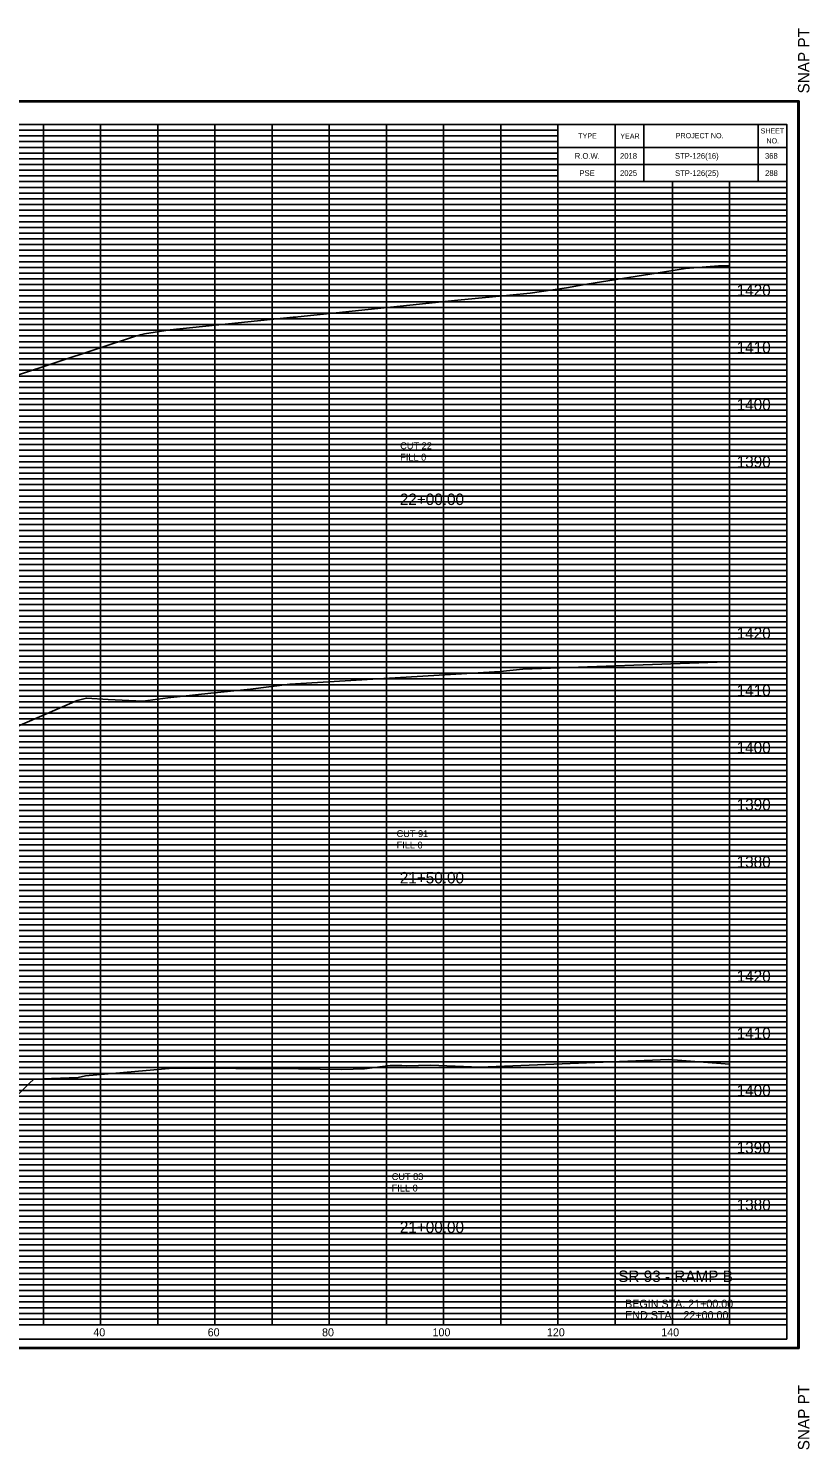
# Model space of a CAD drawing. Extents: x 980 to 1324, y 978 to 1497.
# Drawn here: x 1187.4 to 1324, y 978.2 to 1226.8 of the extents above; entities that cross this region are included whole.
import ezdxf

# ---------------------------------------------------------------- set-up
doc = ezdxf.new("R2010")
doc.units = 0
for name, color, linetype in [('DESIGN - SCRATCH - User 1', 7, 'Continuous'), ('DESIGN - SHEET - Corner Text', 7, 'Continuous'), ('DESIGN - SHEET - Light Grid', 7, 'Continuous'), ('DESIGN - SHEET - Linework', 7, 'Continuous'), ('DESIGN - SHEET - Plot Shape', 7, 'Continuous'), ('DESIGN - TYPICAL - Text', 7, 'Continuous'), ('SURVEY - GROUND - Top of Ground', 7, 'Continuous')]:
    doc.layers.add(name, color=color, linetype=linetype)

# ---------------------------------------------------------------- blocks, each defined once
blk = doc.blocks.new('XSTSHT')
at = {"layer": 'DESIGN - SCRATCH - User 1'}
for p, q in [((28.5, 20.45), (28.5, 20.45)), ((29.24, 20.45), (29.24, 20.45)), ((30.49, 20.45), (30.49, 20.45)), ((31.74, 20.45), (31.74, 20.45)), ((28.5, 20.15), (28.5, 20.15)), ((29.24, 20.15), (29.24, 20.15)), ((30.49, 20.15), (30.49, 20.15)), ((31.74, 20.15), (31.74, 20.15))]:
    blk.add_line(p, q, dxfattribs=at)
at = {"layer": 'DESIGN - SHEET - Light Grid'}
for p, q in [((16, 20.9), (24, 20.9)), ((24, 20.9), (28, 20.9)), ((16, 20.8), (24, 20.8)), ((16, 20.7), (24, 20.7)), ((24, 20.8), (28, 20.8)), ((24, 20.7), (28, 20.7)), ((16, 20.6), (24, 20.6)), ((16, 20.5), (24, 20.5)), ((16, 20.4), (24, 20.4)), ((24, 20.6), (28, 20.6)), ((24, 20.5), (28, 20.5)), ((24, 20.4), (28, 20.4)), ((16, 20.3), (24, 20.3)), ((16, 20.2), (24, 20.2)), ((24, 20.3), (28, 20.3)), ((24, 20.2), (28, 20.2)), ((16, 20.1), (24, 20.1)), ((16, 19.9), (24, 19.9)), ((24, 20.1), (28, 20.1)), ((24, 19.9), (32, 19.9)), ((16, 19.8), (24, 19.8)), ((16, 19.7), (24, 19.7)), ((24, 19.8), (32, 19.8)), ((24, 19.7), (32, 19.7)), ((16, 19.6), (24, 19.6)), ((16, 19.5), (24, 19.5)), ((16, 19.4), (24, 19.4)), ((24, 19.6), (32, 19.6)), ((24, 19.5), (32, 19.5)), ((24, 19.4), (32, 19.4)), ((16, 19.3), (24, 19.3)), ((16, 19.2), (24, 19.2)), ((24, 19.3), (32, 19.3)), ((24, 19.2), (32, 19.2)), ((16, 19.1), (24, 19.1)), ((16, 18.9), (24, 18.9)), ((24, 19.1), (32, 19.1)), ((24, 18.9), (32, 18.9)), ((16, 18.8), (24, 18.8)), ((16, 18.7), (24, 18.7)), ((24, 18.8), (32, 18.8)), ((24, 18.7), (32, 18.7)), ((16, 18.6), (24, 18.6)), ((16, 18.5), (24, 18.5)), ((16, 18.4), (24, 18.4)), ((24, 18.6), (32, 18.6)), ((24, 18.5), (32, 18.5)), ((24, 18.4), (32, 18.4)), ((16, 18.3), (24, 18.3)), ((16, 18.2), (24, 18.2)), ((24, 18.3), (32, 18.3)), ((24, 18.2), (32, 18.2)), ((16, 18.1), (24, 18.1)), ((24, 18.1), (32, 18.1)), ((16, 17.9), (24, 17.9)), ((16, 17.8), (24, 17.8)), ((16, 17.7), (24, 17.7)), ((24, 17.9), (32, 17.9)), ((24, 17.8), (32, 17.8)), ((24, 17.7), (32, 17.7)), ((16, 17.6), (24, 17.6)), ((16, 17.5), (24, 17.5)), ((24, 17.6), (32, 17.6)), ((24, 17.5), (32, 17.5)), ((16, 17.4), (24, 17.4)), ((16, 17.3), (24, 17.3)), ((16, 17.2), (24, 17.2)), ((24, 17.4), (32, 17.4)), ((24, 17.3), (32, 17.3)), ((24, 17.2), (32, 17.2)), ((16, 17.1), (24, 17.1)), ((24, 17.1), (32, 17.1)), ((16, 16.9), (24, 16.9)), ((16, 16.8), (24, 16.8)), ((16, 16.7), (24, 16.7)), ((24, 16.9), (32, 16.9)), ((24, 16.8), (32, 16.8)), ((24, 16.7), (32, 16.7)), ((16, 16.6), (24, 16.6)), ((16, 16.5), (24, 16.5)), ((24, 16.6), (32, 16.6)), ((24, 16.5), (32, 16.5)), ((16, 16.4), (24, 16.4)), ((16, 16.3), (24, 16.3)), ((16, 16.2), (24, 16.2)), ((24, 16.4), (32, 16.4)), ((24, 16.3), (32, 16.3)), ((24, 16.2), (32, 16.2)), ((16, 16.1), (24, 16.1)), ((24, 16.1), (32, 16.1)), ((16, 15.9), (24, 15.9)), ((16, 15.8), (24, 15.8)), ((16, 15.7), (24, 15.7)), ((24, 15.9), (32, 15.9)), ((24, 15.8), (32, 15.8)), ((24, 15.7), (32, 15.7)), ((16, 15.6), (24, 15.6)), ((16, 15.5), (24, 15.5)), ((24, 15.6), (32, 15.6)), ((24, 15.5), (32, 15.5)), ((16, 15.4), (24, 15.4)), ((16, 15.3), (24, 15.3)), ((16, 15.2), (24, 15.2)), ((24, 15.4), (32, 15.4)), ((24, 15.3), (32, 15.3)), ((24, 15.2), (32, 15.2)), ((16, 15.1), (24, 15.1)), ((24, 15.1), (32, 15.1)), ((16, 14.9), (24, 14.9)), ((16, 14.8), (24, 14.8)), ((16, 14.7), (24, 14.7)), ((24, 14.9), (32, 14.9)), ((24, 14.8), (32, 14.8)), ((24, 14.7), (32, 14.7)), ((16, 14.6), (24, 14.6)), ((16, 14.5), (24, 14.5)), ((24, 14.6), (32, 14.6)), ((24, 14.5), (32, 14.5)), ((16, 14.4), (24, 14.4)), ((16, 14.3), (24, 14.3)), ((16, 14.2), (24, 14.2)), ((24, 14.4), (32, 14.4)), ((24, 14.3), (32, 14.3)), ((24, 14.2), (32, 14.2)), ((16, 14.1), (24, 14.1)), ((24, 14.1), (32, 14.1)), ((16, 13.9), (24, 13.9)), ((16, 13.8), (24, 13.8)), ((16, 13.7), (24, 13.7)), ((24, 13.9), (32, 13.9)), ((24, 13.8), (32, 13.8)), ((24, 13.7), (32, 13.7)), ((16, 13.6), (24, 13.6)), ((16, 13.5), (24, 13.5)), ((24, 13.6), (32, 13.6)), ((24, 13.5), (32, 13.5)), ((16, 13.4), (24, 13.4)), ((16, 13.3), (24, 13.3)), ((16, 13.2), (24, 13.2)), ((24, 13.4), (32, 13.4)), ((24, 13.3), (32, 13.3)), ((24, 13.2), (32, 13.2)), ((16, 13.1), (24, 13.1)), ((24, 13.1), (32, 13.1)), ((16, 12.9), (24, 12.9)), ((16, 12.8), (24, 12.8)), ((16, 12.7), (24, 12.7)), ((24, 12.9), (32, 12.9)), ((24, 12.8), (32, 12.8)), ((24, 12.7), (32, 12.7)), ((16, 12.6), (24, 12.6)), ((16, 12.5), (24, 12.5)), ((24, 12.6), (32, 12.6)), ((24, 12.5), (32, 12.5)), ((16, 12.4), (24, 12.4)), ((16, 12.3), (24, 12.3)), ((16, 12.2), (24, 12.2)), ((24, 12.4), (32, 12.4)), ((24, 12.3), (32, 12.3)), ((24, 12.2), (32, 12.2)), ((16, 12.1), (24, 12.1)), ((24, 12.1), (32, 12.1)), ((16, 11.9), (24, 11.9)), ((16, 11.8), (24, 11.8)), ((16, 11.7), (24, 11.7)), ((24, 11.9), (32, 11.9)), ((24, 11.8), (32, 11.8)), ((24, 11.7), (32, 11.7)), ((16, 11.6), (24, 11.6)), ((16, 11.5), (24, 11.5)), ((24, 11.6), (32, 11.6)), ((24, 11.5), (32, 11.5)), ((16, 11.4), (24, 11.4)), ((16, 11.3), (24, 11.3)), ((16, 11.2), (24, 11.2)), ((24, 11.4), (32, 11.4)), ((24, 11.3), (32, 11.3)), ((24, 11.2), (32, 11.2)), ((16, 11.1), (24, 11.1)), ((24, 11.1), (32, 11.1)), ((16, 10.9), (24, 10.9)), ((16, 10.8), (24, 10.8)), ((16, 10.7), (24, 10.7)), ((24, 10.9), (32, 10.9)), ((24, 10.8), (32, 10.8)), ((24, 10.7), (32, 10.7)), ((16, 10.6), (24, 10.6)), ((16, 10.5), (24, 10.5)), ((24, 10.6), (32, 10.6)), ((24, 10.5), (32, 10.5)), ((16, 10.4), (24, 10.4)), ((16, 10.3), (24, 10.3)), ((16, 10.2), (24, 10.2)), ((24, 10.4), (32, 10.4)), ((24, 10.3), (32, 10.3)), ((24, 10.2), (32, 10.2)), ((16, 10.1), (24, 10.1)), ((24, 10.1), (32, 10.1)), ((16, 9.9), (24, 9.9)), ((16, 9.8), (24, 9.8)), ((16, 9.7), (24, 9.7)), ((24, 9.9), (32, 9.9)), ((24, 9.8), (32, 9.8)), ((24, 9.7), (32, 9.7)), ((16, 9.6), (24, 9.6)), ((16, 9.5), (24, 9.5)), ((24, 9.6), (32, 9.6)), ((24, 9.5), (32, 9.5)), ((16, 9.4), (24, 9.4)), ((16, 9.3), (24, 9.3)), ((16, 9.2), (24, 9.2)), ((24, 9.4), (32, 9.4)), ((24, 9.3), (32, 9.3)), ((24, 9.2), (32, 9.2)), ((16, 9.1), (24, 9.1)), ((24, 9.1), (32, 9.1)), ((16, 8.9), (24, 8.9)), ((16, 8.8), (24, 8.8)), ((24, 8.9), (32, 8.9)), ((24, 8.8), (32, 8.8)), ((16, 8.7), (24, 8.7)), ((16, 8.6), (24, 8.6)), ((16, 8.5), (24, 8.5)), ((24, 8.7), (32, 8.7)), ((24, 8.6), (32, 8.6)), ((24, 8.5), (32, 8.5)), ((16, 8.4), (24, 8.4)), ((16, 8.3), (24, 8.3)), ((24, 8.4), (32, 8.4)), ((24, 8.3), (32, 8.3)), ((16, 8.2), (24, 8.2)), ((16, 8.1), (24, 8.1)), ((24, 8.2), (32, 8.2)), ((24, 8.1), (32, 8.1)), ((16, 7.9), (24, 7.9)), ((16, 7.8), (24, 7.8)), ((24, 7.9), (32, 7.9)), ((24, 7.8), (32, 7.8)), ((16, 7.7), (24, 7.7)), ((16, 7.6), (24, 7.6)), ((16, 7.5), (24, 7.5)), ((24, 7.7), (32, 7.7)), ((24, 7.6), (32, 7.6)), ((24, 7.5), (32, 7.5)), ((16, 7.4), (24, 7.4)), ((16, 7.3), (24, 7.3)), ((24, 7.4), (32, 7.4)), ((24, 7.3), (32, 7.3)), ((16, 7.2), (24, 7.2)), ((16, 7.1), (24, 7.1)), ((24, 7.2), (32, 7.2)), ((24, 7.1), (32, 7.1)), ((16, 6.9), (24, 6.9)), ((16, 6.8), (24, 6.8)), ((24, 6.9), (32, 6.9)), ((24, 6.8), (32, 6.8)), ((16, 6.7), (24, 6.7)), ((16, 6.6), (24, 6.6)), ((16, 6.5), (24, 6.5)), ((24, 6.7), (32, 6.7)), ((24, 6.6), (32, 6.6)), ((24, 6.5), (32, 6.5)), ((16, 6.4), (24, 6.4)), ((16, 6.3), (24, 6.3)), ((24, 6.4), (32, 6.4)), ((24, 6.3), (32, 6.3)), ((16, 6.2), (24, 6.2)), ((16, 6.1), (24, 6.1)), ((24, 6.2), (32, 6.2)), ((24, 6.1), (32, 6.1)), ((16, 5.9), (24, 5.9)), ((16, 5.8), (24, 5.8)), ((24, 5.9), (32, 5.9)), ((24, 5.8), (32, 5.8)), ((16, 5.7), (24, 5.7)), ((16, 5.6), (24, 5.6)), ((16, 5.5), (24, 5.5)), ((24, 5.7), (32, 5.7)), ((24, 5.6), (32, 5.6)), ((24, 5.5), (32, 5.5)), ((16, 5.4), (24, 5.4)), ((16, 5.3), (24, 5.3)), ((24, 5.4), (32, 5.4)), ((24, 5.3), (32, 5.3)), ((16, 5.2), (24, 5.2)), ((16, 5.1), (24, 5.1)), ((24, 5.2), (32, 5.2)), ((24, 5.1), (32, 5.1)), ((16, 4.9), (24, 4.9)), ((16, 4.8), (24, 4.8)), ((24, 4.9), (32, 4.9)), ((24, 4.8), (32, 4.8)), ((16, 4.7), (24, 4.7)), ((16, 4.6), (24, 4.6)), ((16, 4.5), (24, 4.5)), ((24, 4.7), (32, 4.7)), ((24, 4.6), (32, 4.6)), ((24, 4.5), (32, 4.5)), ((16, 4.4), (24, 4.4)), ((16, 4.3), (24, 4.3)), ((24, 4.4), (32, 4.4)), ((24, 4.3), (32, 4.3)), ((16, 4.2), (24, 4.2)), ((16, 4.1), (24, 4.1)), ((24, 4.2), (32, 4.2)), ((24, 4.1), (32, 4.1)), ((16, 3.9), (24, 3.9)), ((16, 3.8), (24, 3.8)), ((24, 3.9), (32, 3.9)), ((24, 3.8), (32, 3.8)), ((16, 3.7), (24, 3.7)), ((16, 3.6), (24, 3.6)), ((16, 3.5), (24, 3.5)), ((24, 3.7), (32, 3.7)), ((24, 3.6), (32, 3.6)), ((24, 3.5), (32, 3.5)), ((16, 3.4), (24, 3.4)), ((16, 3.3), (24, 3.3)), ((24, 3.4), (32, 3.4)), ((24, 3.3), (32, 3.3)), ((16, 3.2), (24, 3.2)), ((16, 3.1), (24, 3.1)), ((24, 3.2), (32, 3.2)), ((24, 3.1), (32, 3.1)), ((16, 2.9), (24, 2.9)), ((16, 2.8), (24, 2.8)), ((24, 2.9), (32, 2.9)), ((24, 2.8), (32, 2.8)), ((16, 2.7), (24, 2.7)), ((16, 2.6), (24, 2.6)), ((16, 2.5), (24, 2.5)), ((24, 2.7), (32, 2.7)), ((24, 2.6), (32, 2.6)), ((24, 2.5), (32, 2.5)), ((16, 2.4), (24, 2.4)), ((16, 2.3), (24, 2.3)), ((24, 2.4), (32, 2.4)), ((24, 2.3), (32, 2.3)), ((16, 2.2), (24, 2.2)), ((16, 2.1), (24, 2.1)), ((24, 2.2), (32, 2.2)), ((24, 2.1), (32, 2.1)), ((16, 1.9), (24, 1.9)), ((16, 1.8), (24, 1.8)), ((24, 1.9), (32, 1.9)), ((24, 1.8), (32, 1.8)), ((16, 1.7), (24, 1.7)), ((16, 1.6), (24, 1.6)), ((16, 1.5), (24, 1.5)), ((24, 1.7), (32, 1.7)), ((24, 1.6), (32, 1.6)), ((24, 1.5), (32, 1.5)), ((16, 1.4), (24, 1.4)), ((16, 1.3), (24, 1.3)), ((24, 1.4), (32, 1.4)), ((24, 1.3), (32, 1.3)), ((16, 1.2), (24, 1.2)), ((16, 1.1), (24, 1.1)), ((24, 1.2), (32, 1.2)), ((24, 1.1), (32, 1.1)), ((16, 0.9), (24, 0.9)), ((16, 0.8), (24, 0.8)), ((24, 0.9), (32, 0.9)), ((24, 0.8), (32, 0.8)), ((16, 0.7), (24, 0.7)), ((16, 0.6), (24, 0.6)), ((16, 0.5), (24, 0.5)), ((24, 0.7), (32, 0.7)), ((24, 0.6), (32, 0.6)), ((24, 0.5), (32, 0.5)), ((16, 0.4), (24, 0.4)), ((16, 0.3), (24, 0.3)), ((24, 0.4), (32, 0.4)), ((24, 0.3), (32, 0.3)), ((16, 0.2), (24, 0.2)), ((16, 0.1), (24, 0.1)), ((24, 0.2), (32, 0.2)), ((24, 0.1), (32, 0.1))]:
    blk.add_line(p, q, dxfattribs=at)
at = {"layer": 'DESIGN - SHEET - Linework'}
for p, q in [((-1.823, 21.414), (32.217, 21.414)), ((32.217, 21.414), (32.217, -0.414)), ((19, 0), (19, 21)), ((20, 0), (20, 21)), ((21, 0), (21, 21)), ((22, 0), (22, 21)), ((23, 0), (23, 21)), ((24, 0), (24, 21)), ((25, 0), (25, 21)), ((26, 0), (26, 21)), ((27, 0), (27, 21)), ((0, 20), (28, 20)), ((28, 0), (28, 20)), ((29, 0), (29, 20)), ((30, 0), (30, 20)), ((31, 0), (31, 20)), ((0, 19), (32, 19)), ((0, 18), (32, 18)), ((0, 17), (32, 17)), ((0, 16), (32, 16)), ((0, 15), (32, 15)), ((0, 14), (32, 14)), ((0, 13), (32, 13)), ((0, 12), (32, 12)), ((0, 11), (32, 11)), ((0, 10), (32, 10)), ((0, 9), (32, 9)), ((0, 8), (32, 8)), ((0, 7), (32, 7)), ((0, 6), (32, 6)), ((0, 5), (32, 5)), ((0, 4), (32, 4)), ((0, 3), (32, 3)), ((0, 2), (32, 2)), ((0, 1), (32, 1)), ((-1.823, -0.414), (32.217, -0.414))]:
    blk.add_line(p, q, dxfattribs=at)
for points in [[(0, 21), (0, 0), (32, 0), (32, 21), (0, 21)], [(28, 21), (28, 20), (32, 20), (32, 21), (31.5, 21), (31.5, 20), (29.5, 20), (29.5, 21), (29, 21), (29, 20), (32, 20), (28, 20), (28, 20.3), (32, 20.3), (32, 20.6), (28, 20.6)]]:
    blk.add_lwpolyline(points, dxfattribs=at)
at = {"layer": 'DESIGN - SHEET - Plot Shape'}
for points in [[(-1.803, 21.394), (32.197, 21.394), (32.197, -0.394), (-1.803, -0.394)], [(-0.85, 21), (32, 21), (32, -0.25), (-0.85, -0.25)]]:
    blk.add_lwpolyline(points, close=True, dxfattribs=at)
at = {"layer": 'DESIGN - SHEET - Corner Text'}
for s, p in [('  SNAP PT', (32.397, 21.394)), ('SNAP PT  ', (32.397, -2.194))]:
    blk.add_text(s, height=0.2, rotation=90, dxfattribs=at).set_placement(p)
for s, p in [('SHEET', (31.543, 20.843)), ('TYPE', (28.354, 20.756)), ('YEAR', (29.09, 20.752)), ('PROJECT NO.', (30.06, 20.76)), ('NO.', (31.646, 20.669))]:
    blk.add_text(s, height=0.09, dxfattribs=at).set_placement(p)

msp = doc.modelspace()

# ---------------------------------------------------------------- linework, layer by layer
at = {"layer": 'DESIGN - SHEET - Plot Shape'}
msp.add_lwpolyline([(991.5, 997.5), (1320, 997.5), (1320, 1210), (991.5, 1210)], close=True, dxfattribs=at)
at = {"layer": 'SURVEY - GROUND - Top of Ground'}
for points in [[(1164.27, 1159.14), (1206.27, 1173.02), (1206.99, 1173.22), (1207.71, 1173.36), (1212.2, 1174.1), (1233.68, 1176.27), (1234.2, 1176.31), (1234.5, 1176.34), (1243.98, 1177.34), (1262.49, 1179.29), (1271.56, 1180.16), (1275.12, 1180.49), (1281.51, 1181.44), (1285.05, 1182.09), (1302.32, 1184.81), (1308.06, 1185.26), (1310, 1185.28)], [(1164.36, 1095.59), (1195.93, 1109.23), (1197.53, 1109.66), (1201.33, 1109.39), (1207.41, 1109.12), (1211.76, 1109.71), (1219.28, 1110.5), (1226.24, 1111.24), (1233.1, 1112.11), (1269.87, 1114.33), (1273.88, 1114.72), (1309.47, 1116), (1310, 1116.02)], [(1174.82, 1029.58), (1187.53, 1042.21), (1188.33, 1042.98), (1196.11, 1043.28), (1197.38, 1043.57), (1212.65, 1044.9), (1234.61, 1044.78), (1242.19, 1044.66), (1246.19, 1044.81), (1250.63, 1045.38), (1252.71, 1045.38), (1253.53, 1045.31), (1257.71, 1045.43), (1266.36, 1045.07), (1299.4, 1046.42), (1310, 1045.6)]]:
    msp.add_lwpolyline(points, dxfattribs=at)

# ---------------------------------------------------------------- block references
at = {"layer": 'DESIGN - SHEET - Corner Text', "xscale": 10, "yscale": 10}
msp.add_blockref('XSTSHT', (1000, 1000), dxfattribs=at)

# ---------------------------------------------------------------- texts
at = {"layer": 'DESIGN - SHEET - Corner Text'}
for s, height, p in [('R.O.W.', 1, (1282.94, 1204)), ('2018', 1, (1290.85, 1204)), ('STP-126(16)', 1, (1300.45, 1204)), ('368', 1, (1316.2, 1204)), ('PSE', 1, (1283.75, 1201)), ('2025', 1, (1290.85, 1201)), ('STP-126(25)', 1, (1300.47, 1201)), ('288', 1, (1316.22, 1201)), ('1420', 2, (1311.25, 1180)), ('1410', 2, (1311.25, 1170)), ('1400', 2, (1311.25, 1160)), ('1390', 2, (1311.25, 1150)), ('22+00.00', 2, (1252.34, 1143.43)), ('1420', 2, (1311.25, 1120)), ('1410', 2, (1311.25, 1110)), ('1400', 2, (1311.25, 1100)), ('1390', 2, (1311.25, 1090)), ('1380', 2, (1311.25, 1080)), ('21+50.00', 2, (1252.34, 1077.23)), ('1420', 2, (1311.25, 1060)), ('1410', 2, (1311.25, 1050)), ('1400', 2, (1311.25, 1040)), ('1390', 2, (1311.25, 1030)), ('1380', 2, (1311.25, 1020)), ('21+00.00', 2, (1252.34, 1016.08)), ('SR 93 - RAMP B', 2, (1290.53, 1007.5)), ('BEGIN STA. 21+00.00', 1.4, (1291.75, 1003)), ('END STA.   22+00.00', 1.4, (1291.75, 1001)), ('40', 1.4, (1198.74, 998)), ('60', 1.4, (1218.74, 998)), ('80', 1.4, (1238.74, 998)), ('100', 1.4, (1258.06, 998)), ('120', 1.4, (1278.06, 998)), ('140', 1.4, (1298.06, 998))]:
    msp.add_text(s, height=height, dxfattribs=at).set_placement(p)
at = {"layer": 'DESIGN - TYPICAL - Text'}
for s, p in [('CUT 22', (1252.41, 1153.2)), ('FILL 0', (1252.41, 1151.2)), ('CUT 91', (1251.78, 1085.34)), ('FILL 0', (1251.78, 1083.34)), ('CUT 83', (1250.92, 1025.33)), ('FILL 0', (1250.92, 1023.33))]:
    msp.add_text(s, height=1.2, dxfattribs=at).set_placement(p)

doc.saveas('drawing.dxf')
